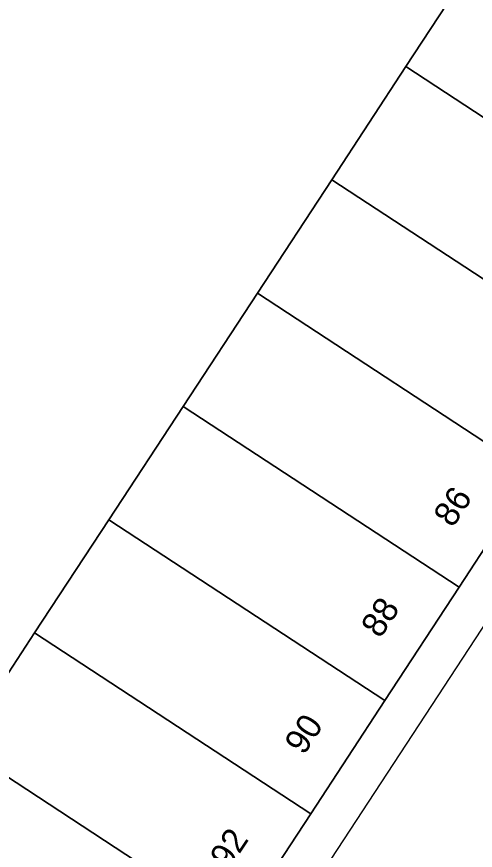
# Model space of a CAD drawing. Extents: x 155640 to 156811, y 382821 to 384049.
# Drawn here: x 156438.39 to 156456.82, y 383747.46 to 383780.99 of the extents above; entities that cross this region are included whole.
import ezdxf

# ---------------------------------------------------------------- set-up
doc = ezdxf.new("R2010")
doc.units = 0
for name, color, linetype in [('IMGEO_Lijnafwatering', 7, 'Continuous'), ('IMGEO_Meer_plas_ven_vijver', 7, 'Continuous'), ('IMGEO_Pand', 7, 'Continuous'), ('IMGEO_Pand_nummerreeks', 7, 'Continuous'), ('IMGEO_Voetgangersgebied_open', 7, 'Continuous')]:
    doc.layers.add(name, color=color, linetype=linetype)

msp = doc.modelspace()

# ---------------------------------------------------------------- linework, layer by layer
at = {"layer": 'IMGEO_Lijnafwatering'}
msp.add_lwpolyline([(156460.088, 383760.982), (156447.726, 383742.098)], dxfattribs=at)
at = {"layer": 'IMGEO_Meer_plas_ven_vijver'}
msp.add_lwpolyline([(156371.545, 383711.205), (156417.388, 383704.778), (156417.887, 383708.339), (156425.336, 383719.667), (156418.225, 383724.315), (156421.209, 383728.871), (156424.193, 383733.426), (156427.177, 383737.982), (156430.161, 383742.537), (156433.145, 383747.093), (156436.129, 383751.648), (156439.113, 383756.204), (156442.097, 383760.76), (156445.081, 383765.315), (156448.065, 383769.871), (156451.049, 383774.426), (156454.033, 383778.982), (156457.017, 383783.537), (156460.001, 383788.093), (156463.557, 383793.358), (156468.974, 383798.024)], dxfattribs=at)
at = {"layer": 'IMGEO_Pand'}
for points in [[(156457.017, 383783.537), (156454.033, 383778.982), (156465.11, 383771.726), (156468.09, 383776.284)], [(156454.033, 383778.982), (156451.049, 383774.426), (156462.129, 383767.169), (156465.11, 383771.726)], [(156451.049, 383774.426), (156448.065, 383769.871), (156459.148, 383762.611), (156462.129, 383767.169)], [(156448.065, 383769.871), (156445.081, 383765.315), (156456.167, 383758.053), (156459.148, 383762.611)], [(156445.081, 383765.315), (156442.097, 383760.76), (156453.187, 383753.496), (156456.167, 383758.053)], [(156442.097, 383760.76), (156439.113, 383756.204), (156450.206, 383748.938), (156453.187, 383753.496)], [(156439.113, 383756.204), (156436.129, 383751.648), (156447.225, 383744.38), (156450.206, 383748.938)], [(156436.129, 383751.648), (156433.145, 383747.093), (156444.244, 383739.822), (156447.225, 383744.38)]]:
    msp.add_lwpolyline(points, close=True, dxfattribs=at)
at = {"layer": 'IMGEO_Voetgangersgebied_open'}
msp.add_lwpolyline([(156466.337, 383744.851), (156469.274, 383749.341), (156472.251, 383753.89), (156475.417, 383758.73), (156475.806, 383758.471), (156483.001, 383769.51), (156481.391, 383771.435), (156477.589, 383775.981), (156471.098, 383780.883), (156468.09, 383776.284), (156465.11, 383771.726), (156462.129, 383767.169), (156459.148, 383762.611), (156456.167, 383758.053), (156453.187, 383753.496), (156450.206, 383748.938), (156447.225, 383744.38)], dxfattribs=at)

# ---------------------------------------------------------------- texts
at = {"layer": 'IMGEO_Pand_nummerreeks'}
for s, p in [('86', (156455.91, 383760.405)), ('88', (156452.997, 383755.951)), ('90', (156449.927, 383751.257)), ('92', (156446.925, 383746.667))]:
    msp.add_text(s, height=1, rotation=56.6197, dxfattribs=at).set_placement(p)

doc.saveas('drawing.dxf')
